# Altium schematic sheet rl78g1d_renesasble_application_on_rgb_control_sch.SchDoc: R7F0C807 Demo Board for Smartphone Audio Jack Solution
size A4; Date: 2014/4/20; Author: Renesas Electronics Corporation; Rev: V1.00; Number: R20UT0784EG0100; Company: Renesas Electronics (China) Co.,Ltd
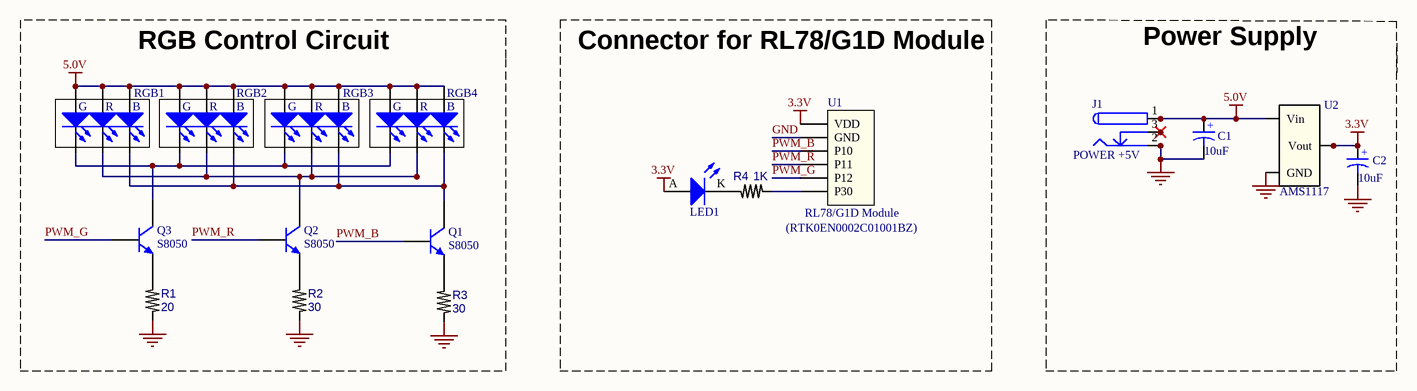
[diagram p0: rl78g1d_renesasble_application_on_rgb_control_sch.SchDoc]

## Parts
C1  10uF  [E10UF]
C2  10uF  [E10UF]
J1  POWER +5V  [POWER IN]
LED1  LED_POWER  [LED 0603]  (value not drawn)
Q1  S8050  [SOT-23B]
Q2  S8050  [SOT-23B]
Q3  S8050  [SOT-23B]
R1  20  [1210]
R2  30  [1210]
R3  30  [1210]
R4  1K  [0603]
RGB1  RGB LED  [RGB]  (value not drawn)
RGB2  RGB LED  [RGB]  (value not drawn)
RGB3  RGB LED  [RGB]  (value not drawn)
RGB4  RGB LED  [RGB]  (value not drawn)
U1  RL78/G1D Module  [G1D Module - 6PIN]
U2  AMS1117  [SOT-223]

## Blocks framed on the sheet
RGB Control Circuit: Q1-Q3 R1-R3 RGB1-RGB4
Connector for RL78/G1D Module: LED1 R4 U1

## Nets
3.3V: C2.1 LED1.A U1.1(VDD) U2.2(Vout) U2.4
5.0V: C1.1 J1.1 J1.1A J1.1B RGB1.1 RGB1.3 RGB1.5 RGB2.1 RGB2.3 RGB2.5 RGB3.1 RGB3.3 RGB3.5 RGB4.1 RGB4.3 RGB4.5 U2.3(Vin)
GND: C1.2 C2.2 J1.2 J1.2A J1.2B R1.1 R2.1 R3.1 U1.2(GND) U2.1(GND)
PWM_B: Q1.1(B) U1.3(P10)
PWM_G: Q3.1(B) U1.5(P12)
PWM_R: Q2.1(B) U1.4(P11)
NetJ1_3: J1.3 J1.3A J1.3B
NetLED1_K: LED1.K R4.2
NetQ1_2: Q1.2(E) R3.2
NetQ1_3: Q1.3(C) RGB1.2 RGB2.2 RGB3.2 RGB4.2
NetQ2_2: Q2.2(E) R2.2
NetQ2_3: Q2.3(C) RGB1.4 RGB2.4 RGB3.4 RGB4.4
NetQ3_2: Q3.2(E) R1.2
NetQ3_3: Q3.3(C) RGB1.6 RGB2.6 RGB3.6 RGB4.6
NetR4_1: R4.1 U1.6(P30)

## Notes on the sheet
- Power Supply
- (RTK0EN0002C01001BZ)

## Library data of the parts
C1 C2 = Cap4: Polarity capacitor (10uF/16V); Value: 100pF
J1 = PWR2.5: Low Voltage Power Supply Connector
LED1 = LED2: Typical RED, GREEN, YELLOW, AMBER GaAs LED
R1-R4 = RES
RGB1-RGB4 = RGB LED: Header, 10-Pin, Dual row
U1 = G1D Module-6
U2 = S1117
